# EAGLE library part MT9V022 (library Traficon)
MICRON 752x480 CMOS SENSOR
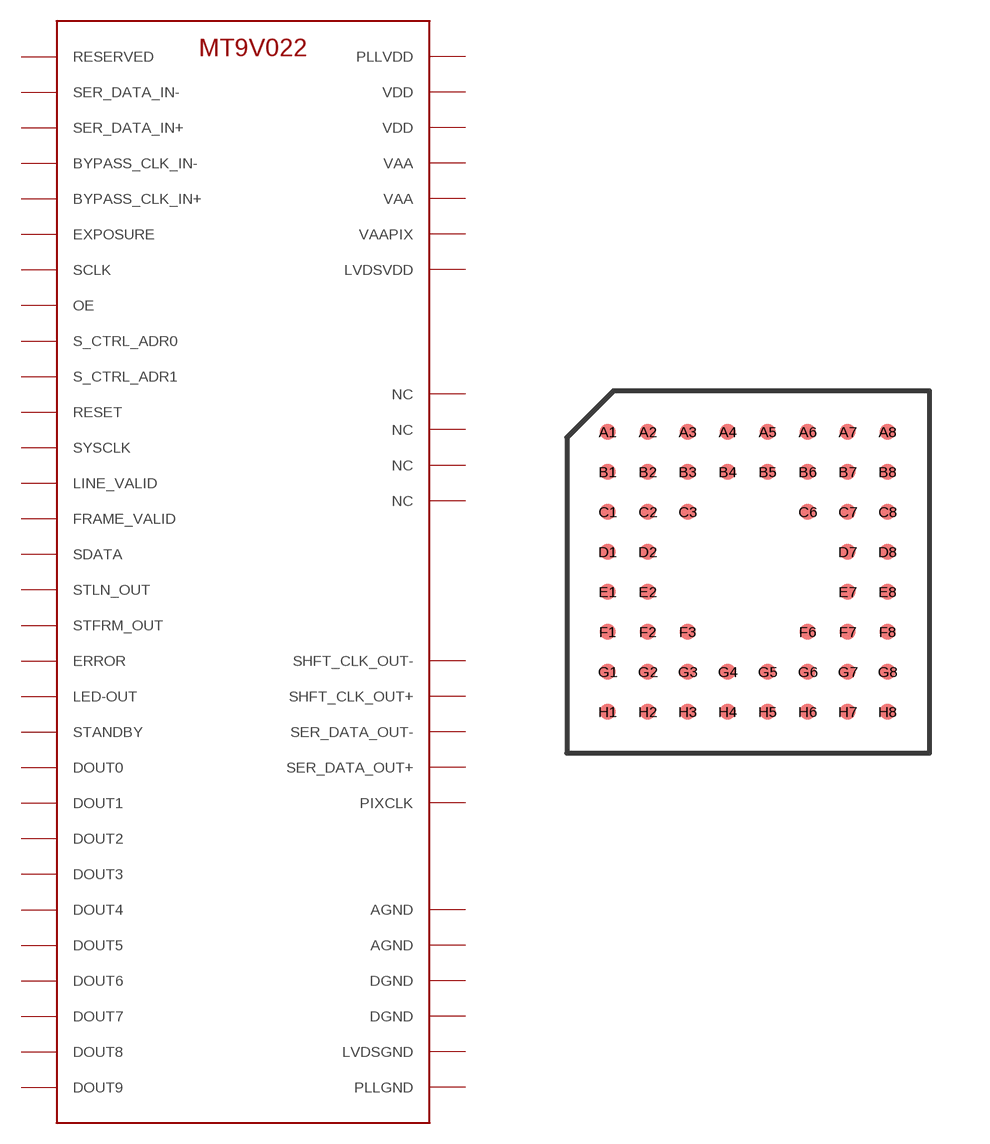
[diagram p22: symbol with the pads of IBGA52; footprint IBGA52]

Designator prefix P

## MT9V022  [IBGA52]
A1  PLLVDD  pwr
A2  SER_DATA_OUT+  out
A3  SER_DATA_OUT-  out
A4  LVDSVDD  pwr
A5  SYSCLK  in
A6  DOUT0  out
A7  DOUT2  out
A8  DOUT3  out
B1  PLLGND  pwr
B2  SHFT_CLK_OUT+  out
B3  SHFT_CLK_OUT-  out
B4  VDD  pwr
B5  PIXCLK  out
B6  DOUT1  out
B7  DOUT4  out
B8  VAAPIX  pwr
C1  BYPASS_CLK_IN+  in
C2  BYPASS_CLK_IN-  in
C3  LVDSGND  pwr
C6  DGND  pwr
C7  AGND  pwr
C8  VAA  pwr
D1  SER_DATA_IN+  in
D2  SER_DATA_IN-  in
D7  NC  nc
D8  NC  nc
E1  DOUT5  out
E2  VDD  pwr
E7  NC  nc
E8  NC  nc
F1  DOUT6  out
F2  DOUT7  out
F3  DGND  pwr
F6  AGND  pwr
F7  VAA  pwr
F8  STANDBY  in
G1  DOUT8  out
G2  FRAME_VALID  out
G3  STLN_OUT
G4  SDATA
G5  STFRM_OUT
G6  LED-OUT  out
G7  S_CTRL_ADR0  in
G8  RESET  in
H1  DOUT9  out
H2  LINE_VALID  out
H3  EXPOSURE  in
H4  SCLK  in
H5  ERROR  out
H6  OE  in
H7  RESERVED  in
H8  S_CTRL_ADR1  in

## Footprint IBGA52 (pad centres in mm)
smd 0.4 x 0.4: A1 -3.5,3.5; A2 -2.5,3.5; A3 -1.5,3.5; A4 -0.5,3.5; A5 0.5,3.5; A6 1.5,3.5; A7 2.5,3.5; A8 3.5,3.5; B1 -3.5,2.5; B2 -2.5,2.5; B3 -1.5,2.5; B4 -0.5,2.5; B5 0.5,2.5; B6 1.5,2.5; B7 2.5,2.5; B8 3.5,2.5; C1 -3.5,1.5; C2 -2.5,1.5; C3 -1.5,1.5; C6 1.5,1.5; C7 2.5,1.5; C8 3.5,1.5; D1 -3.5,0.5; D2 -2.5,0.5; D7 2.5,0.5; D8 3.5,0.5; E1 -3.5,-0.5; E2 -2.5,-0.5; E7 2.5,-0.5; E8 3.5,-0.5; F1 -3.5,-1.5; F2 -2.5,-1.5; F3 -1.5,-1.5; F6 1.5,-1.5; F7 2.5,-1.5; F8 3.5,-1.5; G1 -3.5,-2.5; G2 -2.5,-2.5; G3 -1.5,-2.5; G4 -0.5,-2.5; G5 0.5,-2.5; G6 1.5,-2.5; G7 2.5,-2.5; G8 3.5,-2.5; H1 -3.5,-3.5; H2 -2.5,-3.5; H3 -1.5,-3.5; H4 -0.5,-3.5; H5 0.5,-3.5; H6 1.5,-3.5; H7 2.5,-3.5; H8 3.5,-3.5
